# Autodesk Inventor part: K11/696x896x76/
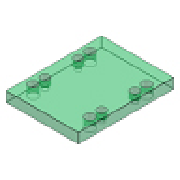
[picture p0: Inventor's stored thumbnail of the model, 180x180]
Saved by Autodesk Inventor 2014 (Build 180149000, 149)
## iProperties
Created: 2009-11
Part Number: K11/696x896x76/
Material: DIN 1.1730
Description: Top Clamping Plate
Document SubType Name: Modeling
Designer: gaom
Standard Revision: 1
Manufacturer: HASCO
Language: en-US
Size Designation: 696x896x76/
Categories: <MemberInstance><Categories><Category DisplayName="Mold" InternalName="349578f2-f4d4-4954-8c09-8e99297a61c0" Mnemonic="MOLD"><Category DisplayName="Mold Plates"
Density: 7.82 g/cm^3
Appearance: Clear - Green 1
IsCustomPart: 1
Author: gaom
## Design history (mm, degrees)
sketch "Sketch1"
  geometry: L1 (-398, 448)-(398, 448); L2 (398, 448)-(398, -448); L3 (398, -448)-(-398, -448); L4 (-398, -448)-(-398, 448); 3 further points
  constraints: 8 end point, 2 midpoint, 2 parallel, 1 horizontal, 1 horizontal alignment, 1 perpendicular, 1 vertical alignment
  dimensions: "d102" = 796 distance between parallel lines of L2 L4 (= W_); "d103" = 896 distance between parallel lines of L3 L1 (= L)
extrude "Extrusion1" new body sketch "Sketch1" distance "d20" = 76 (= H_); taper "d30" = 0 deg
sketch "Sketch2"
  geometry: 3 further points
  dimensions: "d72" = 296 horizontal distance of point (0, 0) point (-296, 337) (= 0.5 x S1_W); "d73" = 296 horizontal distance of point (0, 0) point (-296, 396) (= 0.5 x GP_W); "d74" = 396 vertical distance of point (0, 0) point (-296, 396) (= 0.5 x GP_L); "d75" = 337 vertical distance of point (0, 0) point (-296, 337) (= 0.5 x S1_L)
workplane "Work Plane2"
workplane "Work Plane3"
workplane "Work Plane4"
workplane "Work Plane5"
feature "Sculpt5"
feature "Sculpt6"
body "Solid1"
hole "Hole1" sketch "Sketch2" diameter "d76" = 54 (= GP_d1); stored, may be unused: countersink angle "d80" = 90 deg, drill point angle "d82" = 0 deg; dims "d77" = 6, "d78" = 4, "d79" = 2, "d81" = 76 (= H_)
hole "Hole2" sketch "Sketch2" diameter "d83" = 22 (= S1_d1); stored, may be unused: countersink angle "d87" = 90 deg, drill point angle "d89" = 0 deg; dims "d84" = 6, "d85" = 33 (= S1_d2), "d86" = 26 (= S1_k), "d88" = 76 (= H_)
pattern_linear "Rectangular Pattern1" dims "d92" = 674 (computed from S1_L, Ns), "d95" = 592 (computed from S1_W, Nw)
pattern_linear "Rectangular Pattern2" dims "d98" = 792 (computed from GP_L, Nl), "d101" = 592 (computed from GP_W, Nw)
chamfer "Chamfer1" distance "d104" = 0.5; stored, may be unused: second distance "d105" = 2, angle "d106" = 45 deg
feature "Surface5"
body "Srf5"
feature "Surface6"
body "Srf6"
other parameters: "L" = 896 [user parameter; used in 1 equation term], "W_" = 796 [user parameter; used in 1 equation term], "H_" = 76 [user parameter; used in 3 equation terms], "S1_W" = 592 [user parameter; used in 2 equation terms], "S1_d1" = 22 [user parameter; used in 1 equation term], "S1_d2" = 33 [user parameter; used in 1 equation term], "S1_k" = 26 [user parameter; used in 1 equation term], "S1_L" = 674 [user parameter; used in 2 equation terms], "GP_d1" = 54 [user parameter; used in 1 equation term], "GP_W" = 592 [user parameter; used in 2 equation terms], "GP_L" = 792 [user parameter; used in 2 equation terms], "M_W" = 696 [user parameter], "M_L" = 896 [user parameter]
